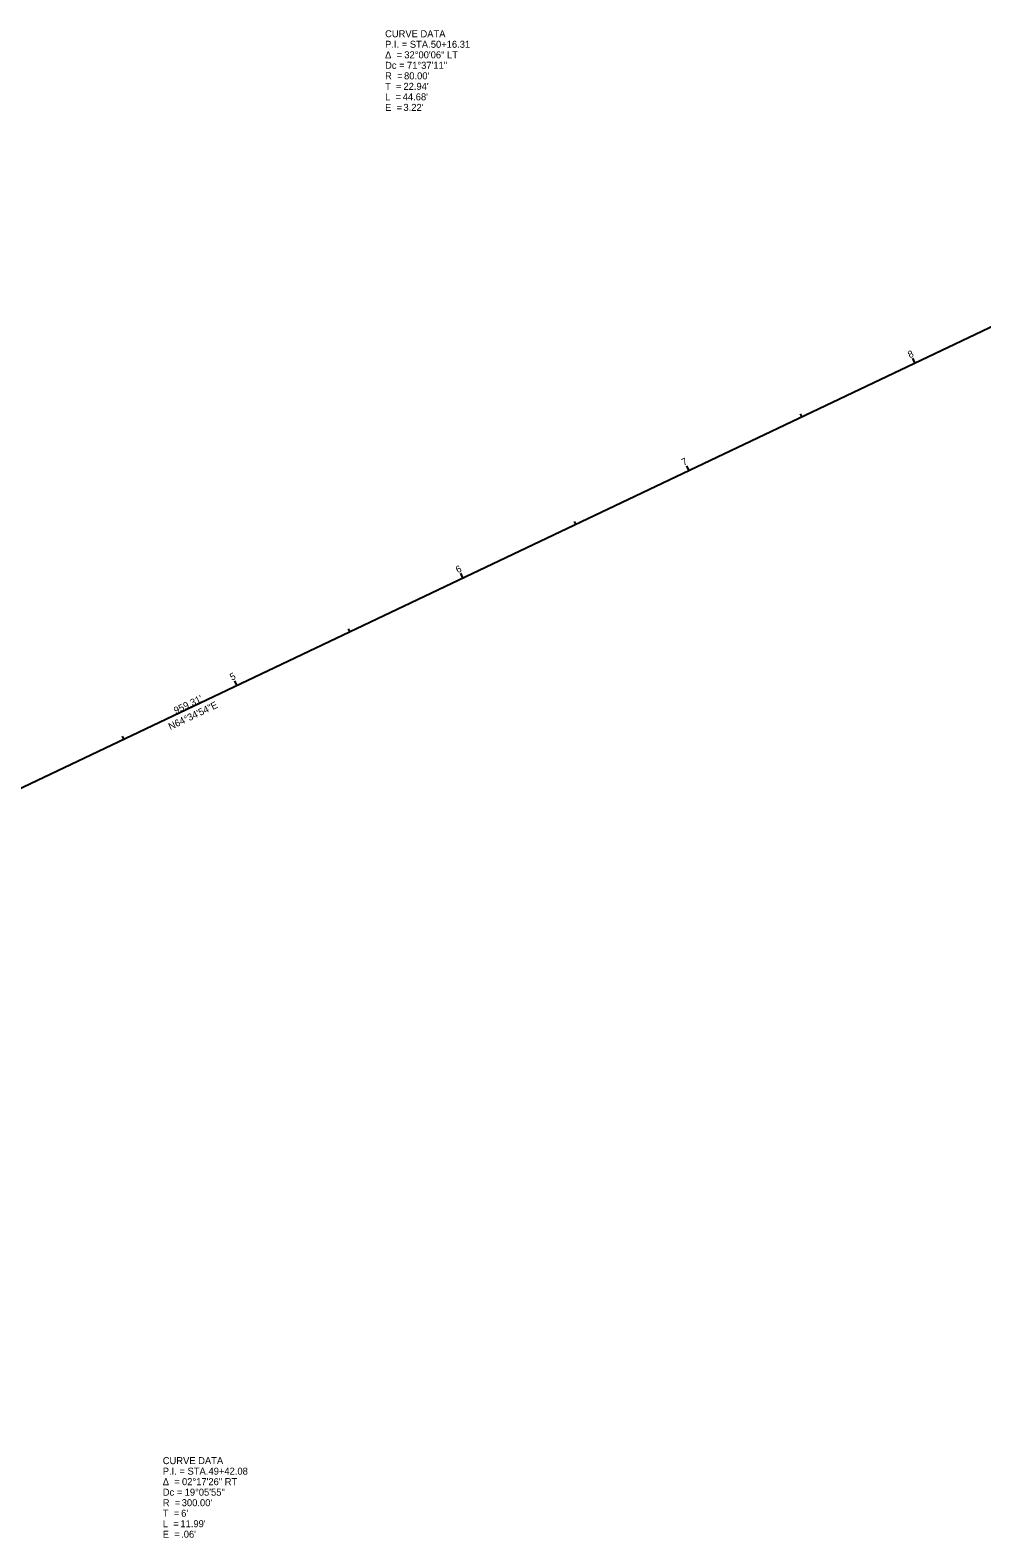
# Model space of a CAD drawing. Extents: x 219353 to 221640, y 361458 to 364236.
# Drawn here: x 219741 to 220121, y 361515 to 362117 of the extents above; entities that cross this region are included whole.
import ezdxf

# ---------------------------------------------------------------- set-up
doc = ezdxf.new("R2010")
doc.units = 0
for name, color, linetype in [('DR_P_Cells', 7, 'Continuous'), ('DR_P_GenericNode', 7, 'Continuous'), ('DR_P_Storm_Sewer', 7, 'Continuous'), ('DT_X_Contour_Major', 7, 'Continuous'), ('SC_ProfileRun1', 7, 'Continuous'), ('SC_ProfileRun3', 7, 'Continuous'), ('SC_Scratch1', 7, 'Continuous'), ('UT_X_Sanitary_Cells', 7, 'Continuous')]:
    doc.layers.add(name, color=color, linetype=linetype)

msp = doc.modelspace()

# ---------------------------------------------------------------- linework, layer by layer
at = {"layer": 'DT_X_Contour_Major'}
msp.add_line((219371.89, 361640.54), (220238.34, 362052.3), dxfattribs=at)
msp.add_line((219371.89, 361640.54), (220238.34, 362052.3), dxfattribs=at)
at = {"layer": 'SC_ProfileRun3'}
for p, q in [((220094.45, 361983.92), (220093.94, 361985.01)), ((220004.13, 361941), (220003.62, 361942.08)), ((219913.81, 361898.08), (219913.3, 361899.16)), ((219823.49, 361855.15), (219822.63, 361856.96))]:
    msp.add_line(p, q, dxfattribs=at)
at = {"layer": 'UT_X_Sanitary_Cells'}
for p, q in [((220094.45, 361983.92), (220093.59, 361985.73)), ((220049.29, 361962.46), (220048.78, 361963.54)), ((220004.13, 361941), (220003.27, 361942.81)), ((219958.97, 361919.54), (219958.46, 361920.62)), ((219913.81, 361898.08), (219912.95, 361899.88)), ((219868.65, 361876.62), (219868.14, 361877.7)), ((219823.49, 361855.15), (219822.63, 361856.96)), ((219778.33, 361833.69), (219777.82, 361834.78))]:
    msp.add_line(p, q, dxfattribs=at)

# ---------------------------------------------------------------- texts
at = {"layer": 'DR_P_Cells'}
msp.add_text("959.31'", height=2.8, rotation=25.41837, dxfattribs=at).set_placement((219799.06, 361843.59))
at = {"layer": 'DR_P_GenericNode'}
msp.add_text("959.31'", height=2.8, rotation=25.41837, dxfattribs=at).set_placement((219799.06, 361843.59))
at = {"layer": 'DR_P_Storm_Sewer'}
for s, p in [('CURVE DATA', (219882.71, 362113.94)), ('P.I. = STA. ', (219882.71, 362109.74)), ('50+16.31', (219900.98, 362109.74)), ('Δ  = ', (219882.71, 362105.54)), ('Dc = ', (219882.71, 362101.34)), ('32°00\'06" LT', (219890.39, 362105.54)), ('71°37\'11"', (219891.45, 362101.34)), ('R  = ', (219882.71, 362097.14)), ("80.00'", (219890.29, 362097.14)), ('T  = ', (219882.71, 362092.94)), ("22.94'", (219890.05, 362092.94)), ('L  = ', (219882.71, 362088.74)), ('E  = ', (219882.71, 362084.54)), ("44.68'", (219889.75, 362088.74)), ("3.22'", (219890.05, 362084.54)), ('CURVE DATA', (219793.87, 361544.1)), ('Δ  = ', (219793.87, 361535.7)), ('P.I. = STA. ', (219793.87, 361539.9)), ('02°17\'26" RT', (219801.55, 361535.7)), ('49+42.08', (219812.14, 361539.9)), ('Dc = ', (219793.87, 361531.5)), ('19°05\'55"', (219802.61, 361531.5)), ('R  = ', (219793.87, 361527.3)), ("300.00'", (219801.45, 361527.3)), ('T  = ', (219793.87, 361523.1)), ('L  = ', (219793.87, 361518.9)), ("11.99'", (219800.91, 361518.9)), ("6'", (219801.21, 361523.1)), ('E  = ', (219793.87, 361514.7)), (".06'", (219801.21, 361514.7))]:
    msp.add_text(s, height=2.8, dxfattribs=at).set_placement(p)
at = {"layer": 'SC_ProfileRun1'}
msp.add_text('N64°34\'54"E', height=2.8, rotation=25.41837, dxfattribs=at).set_placement((219796.91, 361837.21))
at = {"layer": 'SC_ProfileRun3'}
msp.add_text('5', height=2.8, rotation=25.41837, dxfattribs=at).set_placement((219821.45, 361856.95))
at = {"layer": 'SC_Scratch1'}
msp.add_text('N64°34\'54"E', height=2.8, rotation=25.41837, dxfattribs=at).set_placement((219796.91, 361837.21))
at = {"layer": 'UT_X_Sanitary_Cells'}
for s, p in [('8', (220092.39, 361985.71)), ('7', (220001.99, 361942.75)), ('6', (219911.72, 361899.85)), ('5', (219821.45, 361856.95))]:
    msp.add_text(s, height=2.8, rotation=25.41837, dxfattribs=at).set_placement(p)

doc.saveas('drawing.dxf')
